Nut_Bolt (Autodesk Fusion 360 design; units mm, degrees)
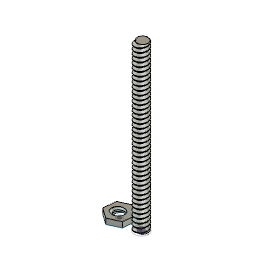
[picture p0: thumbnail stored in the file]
part number: 2025-09-17-21-38-27-805
sketch "Sketch1" plane through (0, 0, 0) normal (0, 0, 1) x axis (1, 0, 0)
  circle C1 centre (0, 0) radius 0.125
  point P1 (0, 0)
  point P2 (0, 0)
  coincident P1 P2
  dimension "d1" diameter C1 = 0.25
extrude "Extrude1" new body sketch "Sketch1" along normal blind 3
thread "Thread1" ThreadOffset 0 ThreadLength 10
sketch "Sketch2" plane through (0, 0, 0) normal (0, 0, 1) x axis (1, 0, 0)
  line L1 (-0.1903, 0.0968) -> (-0.2113, -0.1332)
  line L2 (-0.379, 0.23) -> (-0.1903, 0.0968)
  line L3 (-0.5887, 0.1332) -> (-0.379, 0.23)
  line L4 (-0.6097, -0.0968) -> (-0.5887, 0.1332)
  line L5 (-0.421, -0.23) -> (-0.6097, -0.0968)
  line L6 (-0.2113, -0.1332) -> (-0.421, -0.23)
  circle C1 centre (-0.4, 0) radius 0.125
  point P2 (-0.4, 0)
  point P9 (-0.4, 0)
  coincident P2 P9
  dimension "d6" diameter C1 = 0.25
  dimension "d7" distance P9 L6 = 0.2
extrude "Extrude2" new body sketch "Sketch2" along normal blind 0.1
thread "Thread2" ThreadOffset 0 ThreadLength 10
sketch "Sketch3" plane through (0, 0, 0) normal (0, 0, 1) x axis (1, 0, 0)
